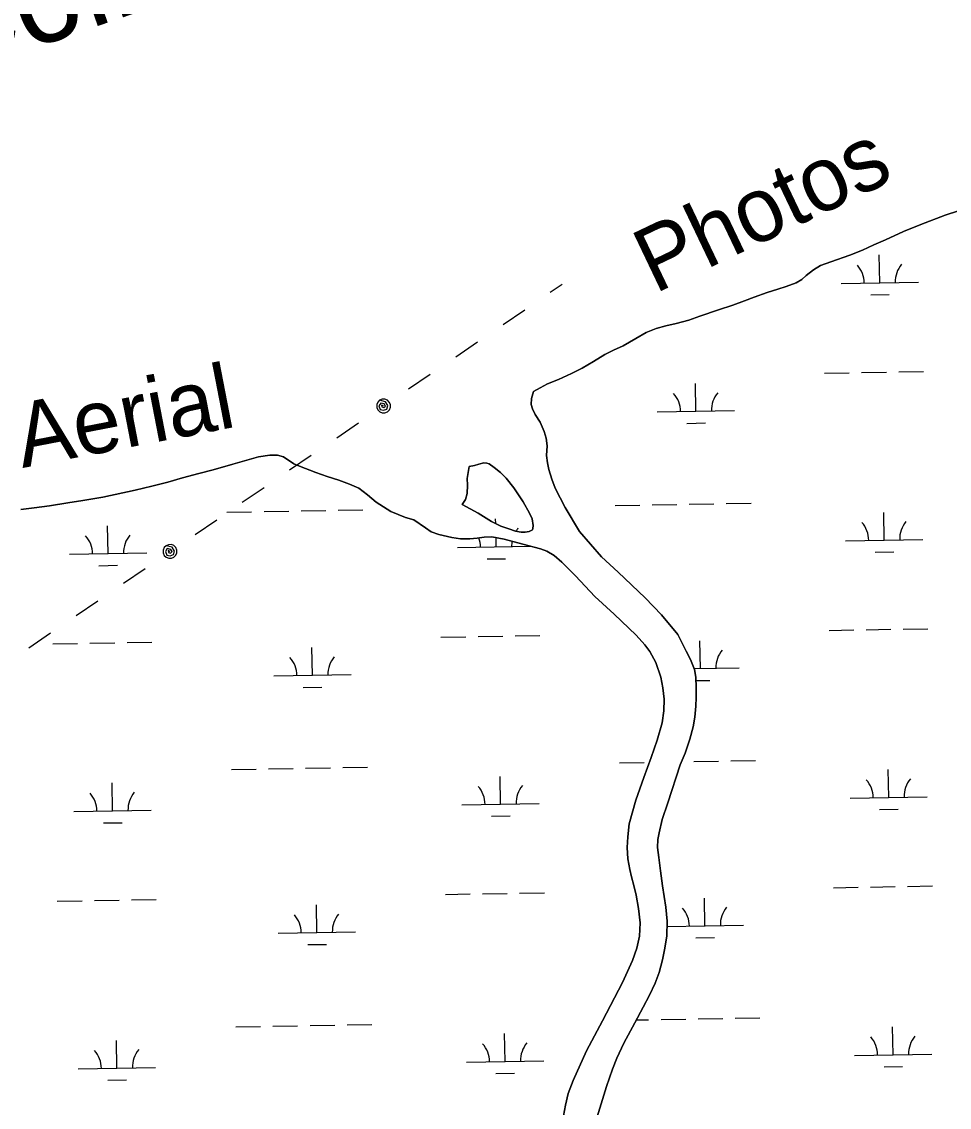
# Model space of a CAD drawing. Extents: x 3892998 to 3931244, y 278583 to 304547.
# Drawn here: x 3915117 to 3916316, y 293226 to 294629 of the extents above; entities that cross this region are included whole.
import ezdxf

# ---------------------------------------------------------------- set-up
doc = ezdxf.new("R2010")
doc.units = 0
for name, color, linetype in [('V-RIVR-IDEN', 7, 'Continuous'), ('V-TOPO-SHOR', 7, 'Continuous'), ('V-UTIL-LINE', 7, 'Continuous'), ('V-WETL-SWMP', 7, 'Continuous')]:
    doc.layers.add(name, color=color, linetype=linetype)

msp = doc.modelspace()

# ---------------------------------------------------------------- linework, layer by layer
at = {"layer": 'V-TOPO-SHOR'}
msp.add_line((3915787.3, 294156.1), (3915778.8, 294151.1), dxfattribs=at)
for points in [[(3916328.2, 294384.7), (3916310.9, 294379.1), (3916279.5, 294367.3), (3916257.1, 294358), (3916233.8, 294347.4), (3916218.6, 294340.7), (3916204, 294334.1), (3916187.8, 294327.5), (3916163.1, 294319), (3916149.9, 294314.1), (3916140.6, 294308.7), (3916131.3, 294301.2), (3916125.8, 294296), (3916118.5, 294291.6), (3916105.5, 294286.8), (3916094.6, 294283.7), (3916080.9, 294279.3), (3916064.2, 294273.1), (3916051.7, 294268.6), (3916036.4, 294263), (3916017.8, 294257), (3915993.8, 294248.6), (3915979.5, 294243.6), (3915963, 294239.3), (3915949.7, 294236.2), (3915937.2, 294232.6), (3915924.2, 294227.3), (3915911.1, 294219.9), (3915894.7, 294210.4), (3915882.3, 294204.8), (3915870.8, 294199.1), (3915856.2, 294189.9), (3915841.5, 294181.2), (3915827.9, 294174.3), (3915811.1, 294166.7), (3915797, 294161.1), (3915787.3, 294156.1)], [(3915778.8, 294151.1), (3915775.9, 294142.3), (3915775.8, 294134.3), (3915777.3, 294128.7), (3915780.8, 294121.4), (3915787.3, 294111.4), (3915792.6, 294099.4), (3915795, 294091.1), (3915796.2, 294080.9), (3915795.5, 294068.3), (3915796.6, 294058.8), (3915798.6, 294050.2), (3915802.2, 294037.8), (3915806.9, 294026.3), (3915819.5, 294001.2), (3915838.2, 293970.4), (3915866.6, 293937.6), (3915888, 293917.5), (3915923.1, 293884.3), (3915944.2, 293862.7), (3915965.2, 293836.9), (3915976.3, 293815.6), (3915981.6, 293804.8), (3915986.9, 293791.7), (3915988.6, 293781.7), (3915989.1, 293768.4), (3915989, 293755.7), (3915988.5, 293744.5), (3915987.1, 293730), (3915985, 293717.5), (3915980.7, 293701.7), (3915974.8, 293683.5), (3915968.2, 293668.7), (3915952.2, 293619.3), (3915945.2, 293598), (3915941, 293580.7), (3915939.3, 293572), (3915939.2, 293561.8), (3915940.7, 293548.7), (3915943, 293531.4), (3915945.4, 293512.2), (3915949.6, 293484.4), (3915951.5, 293466.4), (3915951, 293447.6), (3915948.5, 293431.7), (3915945.6, 293416.5), (3915941.1, 293400), (3915935.9, 293386.3), (3915928.5, 293370.9), (3915920.4, 293355.1), (3915909.6, 293335.2), (3915895.3, 293308.8), (3915886.3, 293289.3), (3915880.8, 293275.1), (3915873.2, 293252.9), (3915867.7, 293235.7), (3915861.2, 293213.7)], [(3915624.1, 293985.4), (3915613.1, 293988.5), (3915594, 293996.1), (3915575.4, 294008.2), (3915563.9, 294017.6), (3915553, 294026.1), (3915540.8, 294031.6), (3915527.1, 294036.6), (3915511.9, 294041.2), (3915497.2, 294046.6), (3915475.9, 294054.6), (3915468.9, 294057.9), (3915455.5, 294066.6), (3915447.8, 294069), (3915437.9, 294069), (3915423, 294066.6), (3915408.2, 294062.6), (3915389.8, 294057.2), (3915364.5, 294049.8), (3915346, 294045), (3915324.9, 294039.7), (3915305.8, 294034.2), (3915285.2, 294028.7), (3915263.6, 294023.6), (3915221.8, 294014.6), (3915195.8, 294010.2), (3915176.7, 294007.2), (3915153, 294003.3), (3915132.9, 294000.7), (3915115.7, 293998.6)], [(3915686.5, 294005.1), (3915707.1, 293993.8), (3915724.2, 293983.1), (3915736.6, 293977.2), (3915747, 293973.5), (3915755.6, 293970.8), (3915762.8, 293969.5), (3915768.1, 293969.3), (3915773.2, 293970.4), (3915777.2, 293972.2), (3915777.9, 293974), (3915778.4, 293977.8), (3915776.8, 293986.6), (3915773.7, 293994.1), (3915765.2, 294008.6), (3915753.3, 294026.6), (3915743.2, 294039.1), (3915735.8, 294046.3), (3915727.8, 294052.8), (3915721.4, 294057.5), (3915718.2, 294058.6), (3915714.4, 294058.9), (3915708.2, 294057.4), (3915702.6, 294055.5), (3915695.6, 294054.2)], [(3915695.6, 294054.2), (3915693.1, 294038.7), (3915693.4, 294030.3), (3915692.9, 294019.2), (3915690.9, 294011.7), (3915686.5, 294005.1)], [(3915816.2, 293207.7), (3915820.2, 293228.4), (3915823.3, 293243.7), (3915830.1, 293260.6), (3915847.1, 293298.8), (3915868, 293337.5), (3915893.6, 293387.3), (3915906.7, 293415.5), (3915912.1, 293431.5), (3915915.6, 293447.1), (3915916.8, 293464.2), (3915914.6, 293482.8), (3915911.3, 293500), (3915908.5, 293512.5), (3915905.3, 293523.8), (3915903.3, 293533.2), (3915900.8, 293546.9), (3915899.7, 293561.5), (3915900.6, 293575.5), (3915902.5, 293592.2), (3915911, 293622.9), (3915921.4, 293652.3), (3915930.8, 293678.2), (3915938.4, 293700.5), (3915945, 293722.8), (3915947.4, 293738.3), (3915947.5, 293753.5), (3915946.1, 293768.3), (3915943.5, 293782.1), (3915937, 293800.7), (3915929.2, 293815.1), (3915922.7, 293823.9), (3915911.5, 293836.1), (3915882.9, 293863.5), (3915858.1, 293886), (3915833, 293912.9), (3915815.3, 293930.6), (3915805.2, 293939.2), (3915796, 293944.8), (3915787.8, 293947.8), (3915765, 293953.9), (3915740.8, 293960.1), (3915724.9, 293963.4), (3915714.7, 293963), (3915705.7, 293961.8), (3915696.2, 293960.7), (3915684.4, 293960.6), (3915672.9, 293962.3), (3915656.1, 293966.5), (3915646.2, 293969.7), (3915639.1, 293975.1), (3915624.1, 293985.4)]]:
    msp.add_lwpolyline(points, dxfattribs=at)
at = {"layer": 'V-UTIL-LINE'}
for points in [[(3915800.4, 294279.6), (3915815.8, 294290.1)], [(3915739.3, 294237.9), (3915767.3, 294257)], [(3915678.1, 294196.2), (3915706.2, 294215.4)], [(3915617, 294154.5), (3915645.1, 294173.7)], [(3915584.7, 294132.6), (3915582.1, 294133.6), (3915582.6, 294131.3), (3915585.2, 294130.4), (3915587.4, 294132.3), (3915585.6, 294135.2), (3915581.1, 294136.2), (3915578.9, 294132.5), (3915580.4, 294127.9), (3915584.9, 294126.9), (3915589, 294128.5), (3915590.4, 294133.2), (3915587.5, 294137.9), (3915579.7, 294140), (3915577.2, 294137.5), (3915575.9, 294134.2), (3915575.9, 294130.7), (3915577.3, 294127.5), (3915579.8, 294125), (3915583.1, 294123.7), (3915586.6, 294123.8), (3915589.8, 294125.1), (3915592.3, 294127.6), (3915593.6, 294130.9), (3915593.6, 294134.4), (3915592.2, 294137.6), (3915589.7, 294140.1), (3915586.4, 294141.4), (3915582.9, 294141.4), (3915579.7, 294140)], [(3915524.4, 294091.4), (3915552.5, 294110.6)], [(3915463.3, 294049.8), (3915491.4, 294068.9)], [(3915402.1, 294008.1), (3915430.2, 294027.2)], [(3915341, 293966.4), (3915369.1, 293985.5)], [(3915308.8, 293944.4), (3915306.1, 293945.5), (3915306.6, 293943.2), (3915309.2, 293942.3), (3915311.5, 293944.2), (3915309.7, 293947.1), (3915305.1, 293948.1), (3915302.9, 293944.4), (3915304.5, 293939.8), (3915308.9, 293938.7), (3915313.1, 293940.4), (3915314.4, 293945), (3915311.6, 293949.8), (3915303.7, 293951.9), (3915301.2, 293949.4), (3915299.9, 293946.1), (3915300, 293942.6), (3915301.3, 293939.4), (3915303.8, 293936.9), (3915307.1, 293935.6), (3915310.6, 293935.6), (3915313.8, 293937), (3915316.3, 293939.5), (3915317.6, 293942.8), (3915317.6, 293946.3), (3915316.2, 293949.5), (3915313.7, 293952), (3915310.4, 293953.3), (3915306.9, 293953.2), (3915303.7, 293951.9)], [(3915248.4, 293903.3), (3915276.5, 293922.5)], [(3915187.3, 293861.6), (3915215.4, 293880.8)], [(3915126.2, 293819.9), (3915154.3, 293839.1)]]:
    msp.add_lwpolyline(points, dxfattribs=at)
at = {"layer": 'V-WETL-SWMP'}
for p, q in [((3916226.4, 294291.7), (3916225.8, 294327.7)), ((3916176.4, 294290.8), (3916276.4, 294292.5)), ((3916214.7, 294276), (3916238.7, 294276.5)), ((3916155, 294175), (3916187, 294175.5)), ((3916203, 294175.8), (3916235, 294176.4)), ((3916251, 294176.7), (3916283, 294177.2)), ((3915988.8, 294125.7), (3915988.2, 294161.7)), ((3915938.8, 294124.8), (3916038.8, 294126.5)), ((3915977.1, 294110), (3916001.1, 294110.5)), ((3915389.8, 294057.2), (3915408.2, 294062.6)), ((3915408.2, 294062.6), (3915423, 294066.6)), ((3915423, 294066.6), (3915437.9, 294069)), ((3915437.9, 294069), (3915447.8, 294068.9)), ((3915447.8, 294068.9), (3915455.5, 294066.6)), ((3915455.5, 294066.6), (3915468.9, 294057.9)), ((3915346, 294045), (3915364.5, 294049.8)), ((3915364.5, 294049.8), (3915389.8, 294057.2)), ((3915468.9, 294057.9), (3915475.9, 294054.6)), ((3915475.9, 294054.6), (3915497.2, 294046.6)), ((3915285.2, 294028.7), (3915305.8, 294034.2)), ((3915305.8, 294034.2), (3915324.9, 294039.7)), ((3915324.9, 294039.7), (3915346, 294045)), ((3915497.2, 294046.6), (3915511.9, 294041.2)), ((3915511.9, 294041.2), (3915527.1, 294036.6)), ((3915527.1, 294036.6), (3915540.8, 294031.6)), ((3915221.8, 294014.6), (3915263.6, 294023.6)), ((3915263.6, 294023.6), (3915285.2, 294028.7)), ((3915540.8, 294031.6), (3915553, 294026.1)), ((3915553, 294026.1), (3915563.9, 294017.6)), ((3915153, 294003.3), (3915176.7, 294007.2)), ((3915176.7, 294007.2), (3915195.8, 294010.2)), ((3915195.8, 294010.2), (3915221.8, 294014.6)), ((3915563.9, 294017.6), (3915575.4, 294008.2)), ((3915575.4, 294008.2), (3915594, 293996.1)), ((3915932, 294004.6), (3915964, 294005.2)), ((3915980, 294005.4), (3916012, 294006)), ((3916028, 294006.3), (3916060, 294006.8)), ((3915115.7, 293998.6), (3915132.9, 294000.7)), ((3915132.9, 294000.7), (3915153, 294003.3)), ((3915382.2, 293995.1), (3915414.2, 293995.6)), ((3915430.2, 293995.9), (3915462.2, 293996.5)), ((3915478.2, 293996.8), (3915510.2, 293997.3)), ((3915526.2, 293997.6), (3915558.2, 293998.1)), ((3915594, 293996.1), (3915613.1, 293988.5)), ((3915884.1, 294003.8), (3915916.1, 294004.3)), ((3916232.2, 293959.1), (3916231.6, 293995)), ((3915228.5, 293941.7), (3915227.9, 293977.7)), ((3915613.1, 293988.5), (3915624.1, 293985.4)), ((3915624.1, 293985.4), (3915639.1, 293975.1)), ((3915729.8, 293980.4), (3915729.7, 293986.4)), ((3915639.1, 293975.1), (3915646.2, 293969.7)), ((3915646.2, 293969.7), (3915656.1, 293966.5)), ((3915656.1, 293966.5), (3915672.9, 293962.3)), ((3915705.7, 293961.8), (3915714.7, 293963)), ((3915714.7, 293963), (3915724.9, 293963.4)), ((3915724.9, 293963.4), (3915740.8, 293960.1)), ((3915672.9, 293962.3), (3915684.4, 293960.6)), ((3915680.4, 293949.5), (3915775.3, 293951.1)), ((3915684.4, 293960.6), (3915696.2, 293960.7)), ((3915696.2, 293960.7), (3915705.7, 293961.8)), ((3915730.4, 293950.4), (3915730.2, 293962.3)), ((3915740.8, 293960.1), (3915765, 293953.9)), ((3915765, 293953.9), (3915787.8, 293947.8)), ((3916182.2, 293958.2), (3916282.2, 293959.9)), ((3915178.5, 293940.8), (3915278.5, 293942.5)), ((3915718.6, 293934.7), (3915742.6, 293935.1)), ((3915787.8, 293947.8), (3915796, 293944.8)), ((3915796, 293944.8), (3915805.2, 293939.2)), ((3915805.2, 293939.2), (3915815.3, 293930.6)), ((3916220.5, 293943.4), (3916244.5, 293943.8)), ((3915216.8, 293926), (3915240.8, 293926.5)), ((3915815.3, 293930.6), (3915833, 293912.9)), ((3915833, 293912.9), (3915858.1, 293886)), ((3915858.1, 293886), (3915882.9, 293863.5)), ((3915882.9, 293863.5), (3915911.5, 293836.1)), ((3916160.8, 293842.4), (3916192.8, 293842.9)), ((3916208.8, 293843.2), (3916240.8, 293843.8)), ((3916256.8, 293844), (3916288.8, 293844.6)), ((3915157.1, 293825), (3915189.1, 293825.5)), ((3915205.1, 293825.8), (3915237.1, 293826.4)), ((3915253.1, 293826.7), (3915285.1, 293827.2)), ((3915659, 293833.7), (3915691, 293834.2)), ((3915707, 293834.5), (3915739, 293835.1)), ((3915755, 293835.3), (3915786.9, 293835.9)), ((3915911.5, 293836.1), (3915922.7, 293823.9)), ((3915922.7, 293823.9), (3915929.2, 293815.1)), ((3915994.6, 293793.1), (3915993.9, 293829)), ((3915492.7, 293784.4), (3915492.1, 293820.4)), ((3915929.2, 293815.1), (3915937, 293800.7)), ((3915937, 293800.7), (3915943.5, 293782.1)), ((3915442.7, 293783.5), (3915542.7, 293785.2)), ((3915943.5, 293782.1), (3915946.1, 293768.3)), ((3915986.4, 293792.9), (3916044.6, 293793.9)), ((3915481, 293768.7), (3915505, 293769.1)), ((3915946.1, 293768.3), (3915947.5, 293753.5)), ((3915988.7, 293777.5), (3916006.8, 293777.8)), ((3915947.5, 293753.5), (3915947.4, 293738.3)), ((3915947.4, 293738.3), (3915945, 293722.8)), ((3915945, 293722.8), (3915938.4, 293700.5)), ((3915938.4, 293700.5), (3915930.8, 293678.2)), ((3915889.8, 293671.2), (3915921.8, 293671.7)), ((3915930.8, 293678.2), (3915921.4, 293652.3)), ((3915985.8, 293672.8), (3916017.8, 293673.4)), ((3916033.8, 293673.6), (3916065.8, 293674.2)), ((3915388, 293662.5), (3915420, 293663)), ((3915436, 293663.3), (3915468, 293663.9)), ((3915484, 293664.1), (3915516, 293664.7)), ((3915532, 293665), (3915564, 293665.5)), ((3916238, 293626.4), (3916237.3, 293662.4)), ((3915234.3, 293609.1), (3915233.7, 293645.1)), ((3915736.1, 293617.7), (3915735.5, 293653.7)), ((3915921.4, 293652.3), (3915911, 293622.9)), ((3916188, 293625.6), (3916287.9, 293627.3)), ((3915686.1, 293616.9), (3915786.1, 293618.6)), ((3915911, 293622.9), (3915902.5, 293592.2)), ((3915184.3, 293608.2), (3915284.3, 293609.9)), ((3915724.4, 293602.1), (3915748.4, 293602.5)), ((3916226.2, 293610.8), (3916250.2, 293611.2)), ((3915222.6, 293593.4), (3915246.6, 293593.8)), ((3915902.5, 293592.2), (3915900.6, 293575.5)), ((3915900.6, 293575.5), (3915899.7, 293561.5)), ((3915899.7, 293561.5), (3915900.8, 293546.9)), ((3915900.8, 293546.9), (3915903.3, 293533.2)), ((3915903.3, 293533.2), (3915905.3, 293523.8)), ((3915905.3, 293523.8), (3915908.5, 293512.5)), ((3915664.7, 293501.1), (3915696.7, 293501.6)), ((3915712.7, 293501.9), (3915744.7, 293502.4)), ((3915760.7, 293502.7), (3915792.7, 293503.3)), ((3915908.5, 293512.5), (3915911.3, 293500)), ((3915911.3, 293500), (3915914.6, 293482.8)), ((3916166.6, 293509.7), (3916198.6, 293510.3)), ((3916214.5, 293510.6), (3916246.5, 293511.1)), ((3916262.5, 293511.4), (3916294.5, 293512)), ((3915162.9, 293492.4), (3915194.9, 293492.9)), ((3915210.9, 293493.2), (3915242.9, 293493.8)), ((3915258.9, 293494), (3915290.9, 293494.6)), ((3915498.5, 293451.7), (3915497.9, 293487.7)), ((3916000.3, 293460.4), (3915999.7, 293496.4)), ((3915914.6, 293482.8), (3915916.8, 293464.2)), ((3915916.8, 293464.2), (3915915.6, 293447.1)), ((3915951.3, 293459.6), (3916050.3, 293461.3)), ((3915448.5, 293450.9), (3915548.5, 293452.6)), ((3915915.6, 293447.1), (3915912.1, 293431.5)), ((3915988.6, 293444.8), (3916012.6, 293445.2)), ((3915486.8, 293436.1), (3915510.8, 293436.5)), ((3915912.1, 293431.5), (3915906.7, 293415.5)), ((3915906.7, 293415.5), (3915893.6, 293387.3)), ((3915893.6, 293387.3), (3915868, 293337.5)), ((3915441.7, 293330.7), (3915473.7, 293331.2)), ((3915489.7, 293331.5), (3915521.7, 293332.1)), ((3915537.7, 293332.3), (3915569.7, 293332.9)), ((3915868, 293337.5), (3915847.1, 293298.8)), ((3915911.5, 293338.8), (3915927.6, 293339.1)), ((3915943.6, 293339.4), (3915975.6, 293339.9)), ((3915991.6, 293340.2), (3916023.6, 293340.7)), ((3916039.5, 293341), (3916071.5, 293341.6)), ((3915393.7, 293329.8), (3915425.7, 293330.4)), ((3915741.9, 293285.1), (3915741.3, 293321.1)), ((3916243.7, 293293.8), (3916243.1, 293329.8)), ((3915240, 293276.4), (3915239.4, 293312.4)), ((3915847.1, 293298.8), (3915830.1, 293260.6)), ((3916193.7, 293292.9), (3916293.7, 293294.7)), ((3915190.1, 293275.6), (3915290, 293277.3)), ((3915691.9, 293284.3), (3915791.9, 293286)), ((3916232, 293278.2), (3916256, 293278.6)), ((3915228.3, 293260.8), (3915252.3, 293261.2)), ((3915730.1, 293269.5), (3915754.1, 293269.9)), ((3915830.1, 293260.6), (3915823.3, 293243.7)), ((3915823.3, 293243.7), (3915820.2, 293228.4)), ((3915820.2, 293228.4), (3915816.2, 293207.7))]:
    msp.add_line(p, q, dxfattribs=at)
for points in [[(3915866.6, 293937.6), (3915838.2, 293970.4), (3915819.5, 294001.2), (3915806.9, 294026.3), (3915802.2, 294037.8), (3915798.6, 294050.2), (3915796.6, 294058.8), (3915795.5, 294068.3), (3915796.2, 294080.9), (3915795, 294091.1), (3915792.6, 294099.4), (3915787.3, 294111.4), (3915780.8, 294121.4), (3915777.3, 294128.7), (3915775.8, 294134.3), (3915775.9, 294142.3), (3915778.8, 294151.1), (3915787.3, 294156.1), (3915797, 294161.1), (3915811.1, 294166.7), (3915827.9, 294174.3), (3915841.5, 294181.2), (3915856.2, 294189.9), (3915870.8, 294199.1), (3915882.3, 294204.8), (3915894.7, 294210.4), (3915911.1, 294219.9), (3915924.2, 294227.3), (3915937.2, 294232.6), (3915949.7, 294236.2), (3915963, 294239.3), (3915979.4, 294243.6), (3915993.8, 294248.6), (3916017.8, 294257), (3916036.4, 294263), (3916051.7, 294268.6), (3916064.2, 294273.1), (3916080.9, 294279.3), (3916094.6, 294283.7), (3916105.5, 294286.8), (3916118.5, 294291.6), (3916125.8, 294296), (3916131.3, 294301.2), (3916140.6, 294308.7), (3916149.9, 294314.1), (3916163.1, 294319), (3916187.8, 294327.5), (3916204, 294334.1), (3916218.6, 294340.7), (3916233.8, 294347.4), (3916257.1, 294358), (3916279.5, 294367.3), (3916310.9, 294379.1), (3916328.2, 294384.7)], [(3915861.2, 293213.7), (3915867.7, 293235.7), (3915873.2, 293252.9), (3915880.8, 293275.1), (3915886.3, 293289.3), (3915895.3, 293308.8), (3915909.6, 293335.2), (3915920.4, 293355.1), (3915928.5, 293370.9), (3915935.9, 293386.3), (3915941.1, 293400), (3915945.6, 293416.5), (3915948.5, 293431.7), (3915951, 293447.6), (3915951.5, 293466.4), (3915949.6, 293484.4), (3915945.4, 293512.2), (3915943, 293531.4), (3915940.7, 293548.7), (3915939.2, 293561.8), (3915939.3, 293572), (3915941, 293580.7), (3915945.2, 293598), (3915952.2, 293619.3), (3915968.2, 293668.7), (3915974.8, 293683.5), (3915980.7, 293701.7), (3915985, 293717.5), (3915987.1, 293730), (3915988.5, 293744.5), (3915989, 293755.7), (3915989.1, 293768.4), (3915988.6, 293781.7), (3915986.9, 293791.7), (3915981.6, 293804.8), (3915976.3, 293815.6), (3915965.2, 293836.9), (3915944.2, 293862.7), (3915923.1, 293884.3), (3915888, 293917.5), (3915866.6, 293937.6)]]:
    msp.add_lwpolyline(points, dxfattribs=at)
msp.add_lwpolyline([(3915686.5, 294005.1), (3915690.9, 294011.7), (3915692.9, 294019.2), (3915693.4, 294030.3), (3915693.1, 294038.7), (3915695.6, 294054.2), (3915702.6, 294055.5), (3915708.2, 294057.4), (3915714.4, 294058.9), (3915718.2, 294058.6), (3915721.4, 294057.5), (3915727.8, 294052.8), (3915735.8, 294046.3), (3915743.2, 294039.1), (3915753.3, 294026.6), (3915765.2, 294008.6), (3915773.7, 293994.1), (3915776.8, 293986.6), (3915778.4, 293977.8), (3915777.9, 293974), (3915777.2, 293972.2), (3915773.2, 293970.4), (3915768.1, 293969.3), (3915762.8, 293969.5), (3915755.6, 293970.8), (3915747, 293973.5), (3915736.6, 293977.2), (3915724.2, 293983.1), (3915707.1, 293993.8)], close=True, dxfattribs=at)
for centre, start, end in [((3916171.2, 294291.2), 0.2199, 41.7635), ((3916281.7, 294293.1), 140.2199, 181.7635), ((3915933.6, 294125.2), 0.2199, 41.7635), ((3916044, 294127.1), 140.2199, 181.7635), ((3916177, 293958.6), 0.2199, 41.7635), ((3916287.4, 293960.5), 140.2199, 181.7635), ((3915173.3, 293941.2), 0.2199, 41.7635), ((3915283.8, 293943.1), 140.2199, 181.7635), ((3915785.6, 293951.8), 140.2199, 147.471), ((3915675.1, 293949.9), 0.2199, 20.29), ((3915785.6, 293951.8), 170.6365, 181.7635), ((3915548, 293785.8), 140.2199, 181.7635), ((3916049.8, 293794.5), 140.2199, 181.7635), ((3915437.5, 293783.9), 0.2199, 41.7635), ((3915680.9, 293617.3), 0.2199, 41.7635), ((3915791.3, 293619.2), 140.2199, 181.7635), ((3916182.7, 293625.9), 0.2199, 41.7635), ((3916293.2, 293627.9), 140.2199, 181.7635), ((3915179, 293608.6), 0.2199, 41.7635), ((3915289.5, 293610.5), 140.2199, 181.7635), ((3915443.2, 293451.3), 0.2199, 41.7635), ((3915553.7, 293453.2), 140.2199, 181.7635), ((3915945.1, 293459.9), 0.2199, 41.7635), ((3916055.5, 293461.9), 140.2199, 181.7635), ((3916298.9, 293295.2), 140.2199, 181.7635), ((3915686.6, 293284.6), 0.2199, 41.7635), ((3915797.1, 293286.5), 140.2199, 181.7635), ((3916188.5, 293293.3), 0.2199, 41.7635), ((3915184.8, 293275.9), 0.2199, 41.7635), ((3915295.3, 293277.9), 140.2199, 181.7635)]:
    msp.add_arc(centre, 35.2, start, end, dxfattribs=at)

# ---------------------------------------------------------------- texts
at = {"layer": 'V-RIVR-IDEN'}
for s, height, rotation, p in [('Collette', 116, 18.973, (3915017.8, 294555.8)), ('Photos', 83, 25.5208, (3915935.4, 294277.1)), ('Aerial', 83, 10.9434, (3915117.8, 294052.2))]:
    msp.add_text(s, height=height, rotation=rotation, dxfattribs=at).set_placement(p)

doc.saveas('drawing.dxf')
